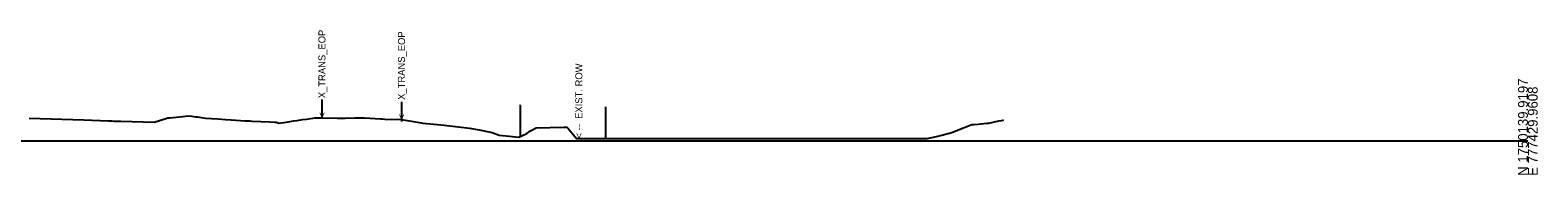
# Model space of a CAD drawing. Extents: x 776426 to 854588, y 1736205 to 1756790.
# Drawn here: x 805244.4 to 805673.6, y 1747205.1 to 1747246.2 of the extents above; entities that cross this region are included whole.
import ezdxf

# ---------------------------------------------------------------- set-up
doc = ezdxf.new("R2010")
doc.units = 0
for name, color, linetype in [('DTM CONTOURS_MAJOR_TX', 7, 'Continuous'), ('DTM_X_FLOW_ARROWS', 7, 'Continuous'), ('TRANS_EOP_PAVED', 7, 'Continuous'), ('X_TRANS_EOP', 7, 'Continuous'), ('XS_X_PAVEMENT', 7, 'Continuous'), ('XS_X_ROW', 7, 'Continuous')]:
    doc.layers.add(name, color=color, linetype=linetype)

msp = doc.modelspace()

# ---------------------------------------------------------------- linework, layer by layer
at = {"layer": 'DTM CONTOURS_MAJOR_TX'}
msp.add_line((805170.79, 1747214.76), (805670.79, 1747214.76), dxfattribs=at)
at = {"layer": 'DTM_X_FLOW_ARROWS'}
msp.add_lwpolyline([(805244.14, 1747221.16), (805259.7, 1747220.66), (805266.64, 1747220.42), (805267.7, 1747220.38), (805268.26, 1747220.36), (805270.21, 1747220.3), (805279.77, 1747220.03), (805282.76, 1747221.03), (805283.58, 1747221.25), (805284.16, 1747221.31), (805287.85, 1747221.69), (805289.34, 1747221.81), (805290.43, 1747221.75), (805291.63, 1747221.55), (805292.03, 1747221.52), (805294.38, 1747221.21), (805296.05, 1747221.06), (805297.85, 1747220.95), (805300.03, 1747220.79), (805301.68, 1747220.71), (805305.67, 1747220.45), (805306.96, 1747220.41), (805307.6, 1747220.35), (805312.63, 1747220.12), (805314.01, 1747220.02), (805314.57, 1747220), (805315.26, 1747219.79), (805317.33, 1747220.08), (805319.49, 1747220.39), (805320.45, 1747220.54), (805321.95, 1747220.79), (805323.11, 1747220.92), (805325.45, 1747221.23), (805327.5, 1747221.28), (805331.8, 1747221.19), (805334.15, 1747221.19), (805336.73, 1747221.24), (805339.6, 1747221.28), (805344.19, 1747220.95), (805344.61, 1747220.94), (805345.38, 1747220.91), (805350.13, 1747220.81), (805355.86, 1747219.81), (805356.19, 1747219.78), (805361.4, 1747219.3), (805366.38, 1747218.71), (805369.49, 1747218.29), (805372.25, 1747217.88), (805375.91, 1747217.09), (805377.93, 1747216.34), (805380.92, 1747216.07), (805383.5, 1747215.77), (805384.6, 1747216.25), (805385.86, 1747216.79), (805386.91, 1747217.6), (805388.49, 1747218.47), (805396.34, 1747218.6), (805397.2, 1747218.61), (805397.66, 1747218.17), (805399.97, 1747215.41), (805400.4, 1747215.41), (805401.53, 1747215.41), (805403.94, 1747215.41), (805431.29, 1747215.41), (805436.1, 1747215.41), (805437.78, 1747215.41), (805445.04, 1747215.41), (805448.42, 1747215.41), (805451.69, 1747215.41), (805454.67, 1747215.41), (805456.63, 1747215.41), (805478.9, 1747215.41), (805479.84, 1747215.41), (805480.8, 1747215.41), (805481.68, 1747215.41), (805483.07, 1747215.41), (805498.55, 1747215.41), (805499.74, 1747215.41), (805502.48, 1747215.94), (805503.92, 1747216.32), (805506.46, 1747216.98), (805507.33, 1747217.29), (805507.99, 1747217.56), (805510.12, 1747218.42), (805512.5, 1747219.33), (805513.13, 1747219.41), (805514.33, 1747219.5), (805516.76, 1747219.73), (805517.37, 1747219.79), (805520.21, 1747220.41), (805521.03, 1747220.54), (805521.5, 1747220.74)], dxfattribs=at)
at = {"layer": 'TRANS_EOP_PAVED'}
for p, q in [((805383.96, 1747224.97), (805383.96, 1747215.97)), ((805383.96, 1747224.97), (805383.96, 1747215.97)), ((805408.21, 1747224.41), (805408.21, 1747215.41)), ((805408.21, 1747224.41), (805408.21, 1747215.41))]:
    msp.add_line(p, q, dxfattribs=at)
at = {"layer": 'X_TRANS_EOP'}
for p, q in [((805327.49, 1747226.51), (805327.49, 1747221.51)), ((805327.49, 1747226.28), (805327.49, 1747221.28)), ((805327.49, 1747226.28), (805327.49, 1747221.28)), ((805350.13, 1747225.81), (805350.13, 1747220.81)), ((805350.13, 1747225.81), (805350.13, 1747220.81)), ((805350.13, 1747225.21), (805350.13, 1747220.21))]:
    msp.add_line(p, q, dxfattribs=at)

# ---------------------------------------------------------------- texts
at = {"layer": 'DTM CONTOURS_MAJOR_TX'}
for s, p in [('N 1750139.9197', (805670.79, 1747204.76)), ('E 777429.9608', (805673.59, 1747204.76))]:
    msp.add_text(s, height=2.8, rotation=90, dxfattribs=at).set_placement(p)
at = {"layer": 'XS_X_PAVEMENT'}
for p in [(805328.49, 1747221.28), (805351.13, 1747220.81)]:
    msp.add_text('< --  X_TRANS_EOP', height=2, rotation=90, dxfattribs=at).set_placement(p)
at = {"layer": 'XS_X_ROW'}
msp.add_text('< --  EXIST. ROW', height=2, rotation=90, dxfattribs=at).set_placement((805401.63, 1747215.41))

doc.saveas('drawing.dxf')
